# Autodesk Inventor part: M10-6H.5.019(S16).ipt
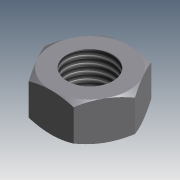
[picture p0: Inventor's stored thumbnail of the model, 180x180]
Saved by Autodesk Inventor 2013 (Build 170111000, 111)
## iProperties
Shininess: 0.0
Length Units: 11269
Angle Units: 11279
Time Units: 11290
Mass Units: 11283
Length Display Precision: 3
Angle Display Precision: 2
Created: 2001-04
Material: Steel, Mild
Document SubType Name: Modeling
Designer: tevgeniy
Mass: 11.2552 g
Surface Area: 10.7859 cm^2
Volume: 1.43196 cm^3
Density: 7.86 g/cm^3
Part Number: M10-6H.5.019(S16).ipt
Density: 0.0
Volumn: 0.0
Area: 0.0
PropertySet Name: Model Information
Control State: 0
Master: False
Checked Out: True
Checked Out Date: 2008-10-15
Last Check In Date: 2008-10-15
Author: tevgeniy
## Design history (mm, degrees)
node "ExtrusionBlind1" dims "d6" = 8.4, "d7" = 0
  sketch "Sketch1"
    geometry: L1 (484.39, 469.325)-(474.575, 469.325); L2 (489.297, 460.825)-(484.39, 469.325); L3 (484.39, 452.325)-(489.297, 460.825); L4 (474.575, 452.325)-(484.39, 452.325); L5 (469.667, 460.825)-(474.575, 452.325); L6 (474.575, 469.325)-(469.667, 460.825); C1 r 8.5 at (479.482, 460.825)
    constraints: 12 end point, 6 tangent, 3 parallel, 1 centre point, 1 horizontal, 1 other
    dimensions: "d1" = 120 deg angle of L1 L2; "d3" = 120 deg angle of L5 L6; "d5" = 17 diameter of C1; "d27" = 17 distance between parallel lines of L4 L1 (derived)
node "ExtrusionThru1" dims "d14" = 0.13, "d15" = 0
  sketch "Sketch2"
    geometry: L1 (-472.982, -455.084)-(-472.482, -455.95); L2 (-479.377, -452.325)-(-478.377, -452.325); L3 (-489.203, -460.662)-(-488.703, -459.796); C1 r 5 at (-479.482, -460.825); C2 r 8.5 at (-479.482, -460.825)
    constraints: 6 end point, 3 tangent, 2 centre point, 1 coincident
    dimensions: "d13" = 10 diameter of C1
node "WorkAxis1"
node "WorkPlane1"
node "RevolutionAngle1" dims "d24" = 360 deg
  sketch "Sketch3"
    geometry: L1 (0, 0)-(0, 8.4); L2 (8.5, 0)-(0, 0); L3 (9.815, 0.759)-(8.5, 0); L4 (9.815, 7.641)-(9.815, 0.759); L5 (8.5, 8.4)-(9.815, 7.641); L6 (0, 8.4)-(8.5, 8.4); L7 (0, 8.4)-(-1, 8.4); L8 (-0.105, 0)-(-1.105, 0); L9 (9.815, 8.4)-(9.815, 7.4); L10 (0, 17.846)-(0, -9.446); L11 (0, 17.846)-(0, -9.446)
    constraints: 22 end point, 4 collinear, 2 horizontal, 2 vertical
    dimensions: "d17" = 8.5 distance of L1.end L5.start; "d19" = 30 deg angle of L6 L5; "d21" = 30 deg angle of L3 L2; "d23" = 0 horizontal distance of L5.start L2.start
thread "Thread1" dims "d25" = 10, "d26" = 0
body "Solid1"
other parameters: "d0" = 120 deg (derived), "d2" = 120 deg (derived), "d4" = 17 (derived), "d8" = 0, "d9" = 0, "d10" = 0, "d11" = 0, "d16" = 8.5 (derived), "d18" = 30 deg (derived), "d20" = 30 deg (derived), "d22" = 0 (derived), "d28" = 0
